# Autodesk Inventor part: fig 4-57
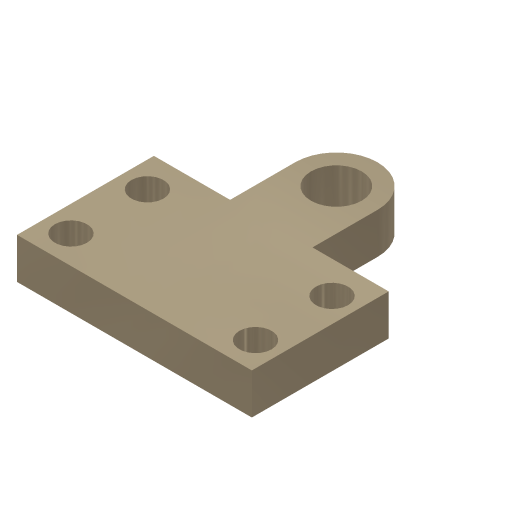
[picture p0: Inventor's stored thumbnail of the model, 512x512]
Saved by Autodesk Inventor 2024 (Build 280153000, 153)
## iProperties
Created: 2004-05
Part Number: fig 4-57
Document SubType Name: Modeling
Designer: CADCIM Technologies
Manufacturer: Standard
Standards Organization: Custom
Density: 1 g/cm^3
Material: Generic
Appearance: Metal-Titanium (Polished)
Author: CADCIM Technologies
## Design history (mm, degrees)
sketch "Sketch1"
  geometry: L1 (39.729, 55.62)-(39.729, 42.054); L2 (39.729, 42.054)-(23.837, 42.054); L3 (23.837, 42.054)-(23.837, 13.516); L4 (23.837, 13.516)-(72.804, 13.516); L5 (72.804, 13.516)-(72.804, 42.054); L6 (72.804, 42.054)-(56.912, 42.054); L7 (56.912, 42.054)-(56.912, 55.62); C1 r 3.354 at (29.212, 35.336); C2 r 3.354 at (29.212, 19.383); C3 r 3.354 at (67.7, 35.336); C4 r 3.354 at (67.7, 19.383); C5 r 5.297 at (48.32, 55.62); A1 r 8.592 centre (48.32, 55.62) between (56.912, 55.62) and (39.729, 55.62)
  constraints: 14 end point, 6 centre point, 4 parallel, 2 equal length, 2 horizontal alignment, 2 point on circle, 2 tangent, 2 vertical alignment, 1 coincident, 1 collinear, 1 perpendicular, 1 vertical
extrude "Extrusion1" new body sketch "Sketch1" distance "d0" = 8.5; taper "d1" = 0 deg
body "Solid1"
